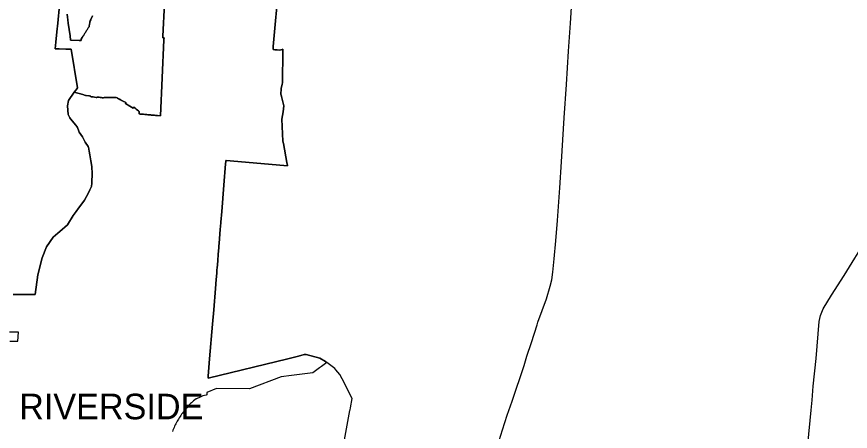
# Model space of a CAD drawing. Extents: x 0 to 34, y 0 to 22.
# Drawn here: x 5.3732 to 5.6354, y 15.5639 to 15.6943 of the extents above; entities that cross this region are included whole.
import ezdxf

# ---------------------------------------------------------------- set-up
doc = ezdxf.new("R2010")
doc.units = 0
for name, color, linetype in [('GM_X_Corporation', 7, 'Continuous'), ('GM_X_Corporation_Text', 7, 'Continuous'), ('GM_X_State_Route', 7, 'Continuous')]:
    doc.layers.add(name, color=color, linetype=linetype)

msp = doc.modelspace()

# ---------------------------------------------------------------- linework, layer by layer
at = {"layer": 'GM_X_Corporation'}
for points in [[(5.45565, 15.70458), (5.45394, 15.68495), (5.4539, 15.68447), (5.45386, 15.68399), (5.45443, 15.68394), (5.45515, 15.68387), (5.45602, 15.68379), (5.45634, 15.6839), (5.45641, 15.68392), (5.45695, 15.6841), (5.45695, 15.68396), (5.45695, 15.68351), (5.45688, 15.67362), (5.45688, 15.67347), (5.45677, 15.6731), (5.45639, 15.67177), (5.45634, 15.66989), (5.45638, 15.66974), (5.45652, 15.66919), (5.45729, 15.66627), (5.45701, 15.66442), (5.45665, 15.6621), (5.45698, 15.65516), (5.45712, 15.65441), (5.45825, 15.64847), (5.45836, 15.64789), (5.45841, 15.64761), (5.45844, 15.64743), (5.4573, 15.64753), (5.43915, 15.64911), (5.43903, 15.64912), (5.43899, 15.64863), (5.43895, 15.64815), (5.43895, 15.64807), (5.4384, 15.64136), (5.43772, 15.63301), (5.43745, 15.62972), (5.43743, 15.62943), (5.43726, 15.62736), (5.43691, 15.62308), (5.43689, 15.6229), (5.43685, 15.62235), (5.43679, 15.62162), (5.43662, 15.6196), (5.43646, 15.61754), (5.43627, 15.61522), (5.43623, 15.61475), (5.43621, 15.61449), (5.4362, 15.61442), (5.43616, 15.61396), (5.43614, 15.61362), (5.43598, 15.61164), (5.43575, 15.60878), (5.43526, 15.60216), (5.43525, 15.60208), (5.43481, 15.59761), (5.43393, 15.58667), (5.43349, 15.58122), (5.43344, 15.58058), (5.45847, 15.58674), (5.46192, 15.58759), (5.46369, 15.58803), (5.46388, 15.58808), (5.46428, 15.58803), (5.46854, 15.5869), (5.47038, 15.58585), (5.47043, 15.5858), (5.47076, 15.5855), (5.47037, 15.58523), (5.46908, 15.58432), (5.46848, 15.58389), (5.46641, 15.58228), (5.4597, 15.58146), (5.45643, 15.58102), (5.44643, 15.57724), (5.43612, 15.57736), (5.43307, 15.57609), (5.43301, 15.57535), (5.43285, 15.57531), (5.4318, 15.57508), (5.43091, 15.57466), (5.42976, 15.57412), (5.42972, 15.5741), (5.42882, 15.57347), (5.42854, 15.57321), (5.42853, 15.57321), (5.42822, 15.57291), (5.4279, 15.5726), (5.4276, 15.57229), (5.4273, 15.57198), (5.427, 15.57165), (5.42671, 15.57133), (5.42643, 15.571), (5.42615, 15.57066), (5.42588, 15.57032), (5.42561, 15.56997), (5.42536, 15.56962), (5.4251, 15.56927), (5.42485, 15.56891), (5.42461, 15.56854), (5.42438, 15.56818), (5.42413, 15.56777), (5.42393, 15.56743), (5.42371, 15.56705), (5.42351, 15.56666), (5.4233, 15.56628), (5.42311, 15.56589), (5.42292, 15.56549), (5.42274, 15.5651), (5.42257, 15.5647), (5.4224, 15.56429), (5.42224, 15.56389)], [(5.4763, 15.56125), (5.47806, 15.57044), (5.4781, 15.57063), (5.47823, 15.57133), (5.47878, 15.5742), (5.4756, 15.58039), (5.47483, 15.58178), (5.47364, 15.5832), (5.4733, 15.58361), (5.47076, 15.5855), (5.47043, 15.5858), (5.47038, 15.58585), (5.46854, 15.5869), (5.46428, 15.58803), (5.46388, 15.58808), (5.46369, 15.58803), (5.46192, 15.58759), (5.45847, 15.58674), (5.43344, 15.58058), (5.43349, 15.58122), (5.43393, 15.58667), (5.43481, 15.59761), (5.43525, 15.60208), (5.43526, 15.60216), (5.43575, 15.60878), (5.43598, 15.61164), (5.43614, 15.61362), (5.43616, 15.61396), (5.43621, 15.61449), (5.43623, 15.61475), (5.43627, 15.61522), (5.43646, 15.61754), (5.43662, 15.6196), (5.43679, 15.62162), (5.43685, 15.62235), (5.43689, 15.6229), (5.43691, 15.62308), (5.43726, 15.62736), (5.43743, 15.62943), (5.43745, 15.62972), (5.43772, 15.63301), (5.4384, 15.64136), (5.43895, 15.64807), (5.43895, 15.64815), (5.43899, 15.64863), (5.43903, 15.64912), (5.43915, 15.64911), (5.4573, 15.64753), (5.45844, 15.64743), (5.45841, 15.64761), (5.45836, 15.64789), (5.45825, 15.64847), (5.45712, 15.65441), (5.45698, 15.65516), (5.45665, 15.6621), (5.45701, 15.66442), (5.45729, 15.66627), (5.45652, 15.66919), (5.45638, 15.66974), (5.45634, 15.66989), (5.45639, 15.67177), (5.45677, 15.6731), (5.45688, 15.67347), (5.45688, 15.67362), (5.45695, 15.68351), (5.45695, 15.68396), (5.45695, 15.6841), (5.45641, 15.68392), (5.45634, 15.6839), (5.45602, 15.68379), (5.45515, 15.68387), (5.45443, 15.68394), (5.45386, 15.68399), (5.45394, 15.68495), (5.45565, 15.70458)], [(5.37215, 15.60695), (5.37461, 15.60695), (5.37468, 15.60695), (5.37697, 15.60695), (5.37715, 15.60694), (5.37758, 15.60694), (5.37797, 15.60694), (5.37819, 15.60694), (5.37908, 15.60694), (5.37994, 15.61307), (5.38121, 15.61847), (5.38261, 15.62195), (5.38467, 15.62497), (5.38618, 15.62627), (5.38678, 15.62679), (5.38917, 15.62886), (5.39099, 15.63177), (5.3919, 15.633), (5.39273, 15.63414), (5.39305, 15.63457), (5.39457, 15.63664), (5.39521, 15.63774), (5.39528, 15.63785), (5.39624, 15.63982), (5.39675, 15.64086), (5.39682, 15.64195), (5.39684, 15.64223), (5.39699, 15.64486), (5.39687, 15.64725), (5.3966, 15.64894), (5.39623, 15.65087), (5.39602, 15.65198), (5.39578, 15.65324), (5.39572, 15.65354), (5.3948, 15.65487), (5.39389, 15.65652), (5.39292, 15.65801), (5.39281, 15.65818), (5.39277, 15.65832), (5.3924, 15.65943), (5.39215, 15.65979), (5.39185, 15.66023), (5.39011, 15.66222), (5.38997, 15.6625), (5.38944, 15.66353), (5.38918, 15.66628), (5.38951, 15.66794), (5.39136, 15.67053), (5.39407, 15.6698), (5.3949, 15.66957), (5.39506, 15.66953), (5.39588, 15.66941), (5.39607, 15.66939), (5.39612, 15.66938), (5.39631, 15.66936), (5.39643, 15.66934), (5.3966, 15.66932), (5.39658, 15.66916), (5.39665, 15.66915), (5.39678, 15.66913), (5.39725, 15.66906), (5.39773, 15.669), (5.39821, 15.66893), (5.39849, 15.6689), (5.39851, 15.66905), (5.3987, 15.66903), (5.39899, 15.66899), (5.39918, 15.66896), (5.39947, 15.66892), (5.39966, 15.6689), (5.39994, 15.66886), (5.40013, 15.66883), (5.40055, 15.66884), (5.40074, 15.66885), (5.40103, 15.66885), (5.40122, 15.66886), (5.40152, 15.66886), (5.4017, 15.66887), (5.402, 15.66887), (5.40219, 15.66888), (5.40248, 15.66888), (5.40267, 15.66889), (5.40296, 15.66889), (5.40315, 15.6689), (5.40344, 15.6689), (5.40363, 15.66891), (5.40393, 15.66891), (5.40411, 15.66892), (5.40438, 15.66892), (5.40446, 15.66892), (5.40456, 15.66887), (5.40479, 15.66875), (5.40494, 15.66867), (5.40522, 15.66853), (5.40537, 15.66845), (5.40564, 15.66831), (5.4058, 15.66823), (5.40607, 15.66809), (5.40622, 15.66801), (5.4065, 15.66787), (5.40665, 15.66779), (5.40672, 15.66776), (5.40687, 15.66768), (5.40714, 15.66754), (5.40734, 15.66744), (5.40757, 15.66731), (5.40742, 15.66703), (5.40878, 15.6662), (5.40982, 15.66556), (5.41007, 15.66587), (5.4101, 15.66585), (5.41045, 15.66557), (5.41048, 15.66555), (5.41083, 15.66528), (5.41086, 15.66525), (5.41124, 15.66495), (5.41154, 15.66472), (5.41176, 15.66455), (5.41176, 15.66452), (5.41172, 15.66374), (5.4121, 15.66371), (5.4122, 15.6637), (5.41258, 15.66366), (5.41268, 15.66365), (5.41306, 15.66362), (5.41316, 15.66361), (5.41354, 15.66358), (5.41364, 15.66357), (5.41402, 15.66353), (5.41412, 15.66352), (5.4145, 15.66349), (5.4146, 15.66348), (5.41498, 15.66344), (5.41508, 15.66343), (5.41546, 15.6634), (5.41556, 15.66339), (5.41594, 15.66336), (5.41605, 15.66335), (5.41642, 15.66331), (5.41653, 15.6633), (5.4169, 15.66327), (5.41701, 15.66326), (5.41746, 15.66322), (5.41749, 15.66321), (5.41842, 15.66313), (5.41955, 15.68699), (5.41956, 15.68706), (5.41956, 15.68715), (5.41958, 15.68763), (5.41917, 15.68767), (5.41917, 15.68767), (5.4192, 15.68816), (5.4197, 15.69842)], [(5.4197, 15.69842), (5.4192, 15.68816), (5.41917, 15.68767), (5.41917, 15.68767), (5.41958, 15.68763), (5.41956, 15.68715), (5.41956, 15.68706), (5.41955, 15.68699), (5.41842, 15.66313), (5.41749, 15.66321), (5.41746, 15.66322), (5.41701, 15.66326), (5.4169, 15.66327), (5.41653, 15.6633), (5.41642, 15.66331), (5.41605, 15.66335), (5.41594, 15.66336), (5.41556, 15.66339), (5.41546, 15.6634), (5.41508, 15.66343), (5.41498, 15.66344), (5.4146, 15.66348), (5.4145, 15.66349), (5.41412, 15.66352), (5.41402, 15.66353), (5.41364, 15.66357), (5.41354, 15.66358), (5.41316, 15.66361), (5.41306, 15.66362), (5.41268, 15.66365), (5.41258, 15.66366), (5.4122, 15.6637), (5.4121, 15.66371), (5.41172, 15.66374), (5.41176, 15.66452), (5.41176, 15.66455), (5.41154, 15.66472), (5.41124, 15.66495), (5.41086, 15.66525), (5.41083, 15.66528), (5.41048, 15.66555), (5.41045, 15.66557), (5.4101, 15.66585), (5.41007, 15.66587), (5.40982, 15.66556), (5.40878, 15.6662), (5.40742, 15.66703), (5.40757, 15.66731), (5.40734, 15.66744), (5.40714, 15.66754), (5.40687, 15.66768), (5.40672, 15.66776), (5.40665, 15.66779), (5.4065, 15.66787), (5.40622, 15.66801), (5.40607, 15.66809), (5.4058, 15.66823), (5.40564, 15.66831), (5.40537, 15.66845), (5.40522, 15.66853), (5.40494, 15.66867), (5.40479, 15.66875), (5.40456, 15.66887), (5.40446, 15.66892), (5.40438, 15.66892), (5.40411, 15.66892), (5.40393, 15.66891), (5.40363, 15.66891), (5.40344, 15.6689), (5.40315, 15.6689), (5.40296, 15.66889), (5.40267, 15.66889), (5.40248, 15.66888), (5.40219, 15.66888), (5.402, 15.66887), (5.4017, 15.66887), (5.40152, 15.66886), (5.40122, 15.66886), (5.40103, 15.66885), (5.40074, 15.66885), (5.40055, 15.66884), (5.40013, 15.66883), (5.39994, 15.66886), (5.39966, 15.6689), (5.39947, 15.66892), (5.39918, 15.66896), (5.39899, 15.66899), (5.3987, 15.66903), (5.39851, 15.66905), (5.39849, 15.6689), (5.39821, 15.66893), (5.39773, 15.669), (5.39725, 15.66906), (5.39678, 15.66913), (5.39665, 15.66915), (5.39658, 15.66916), (5.3966, 15.66932), (5.39643, 15.66934), (5.39631, 15.66936), (5.39612, 15.66938), (5.39607, 15.66939), (5.39588, 15.66941), (5.39506, 15.66953), (5.3949, 15.66957), (5.39407, 15.6698), (5.39136, 15.67053), (5.39196, 15.67136), (5.3924, 15.67197), (5.39032, 15.68413), (5.38967, 15.68413), (5.38872, 15.68415), (5.38662, 15.68417), (5.38658, 15.68417), (5.38531, 15.68419), (5.38552, 15.68626), (5.38584, 15.68951), (5.38613, 15.69231), (5.38669, 15.69795)], [(5.38669, 15.69795), (5.38613, 15.69231), (5.38584, 15.68951), (5.38552, 15.68626), (5.38531, 15.68419), (5.38658, 15.68417), (5.38662, 15.68417), (5.38872, 15.68415), (5.38967, 15.68413), (5.39032, 15.68413), (5.3924, 15.67197), (5.39196, 15.67136), (5.39136, 15.67053), (5.38951, 15.66794), (5.38918, 15.66628), (5.38944, 15.66353), (5.38997, 15.6625), (5.39011, 15.66222), (5.39185, 15.66023), (5.39215, 15.65979), (5.3924, 15.65943), (5.39277, 15.65832), (5.39281, 15.65818), (5.39292, 15.65801), (5.39389, 15.65652), (5.3948, 15.65487), (5.39572, 15.65354), (5.39578, 15.65324), (5.39602, 15.65198), (5.39623, 15.65087), (5.3966, 15.64894), (5.39687, 15.64725), (5.39699, 15.64486), (5.39684, 15.64223), (5.39682, 15.64195), (5.39675, 15.64086), (5.39624, 15.63982), (5.39528, 15.63785), (5.39521, 15.63774), (5.39457, 15.63664), (5.39305, 15.63457), (5.39273, 15.63414), (5.3919, 15.633), (5.39099, 15.63177), (5.38917, 15.62886), (5.38678, 15.62679), (5.38618, 15.62627), (5.38467, 15.62497), (5.38261, 15.62195), (5.38121, 15.61847), (5.37994, 15.61307), (5.37908, 15.60694), (5.37819, 15.60694), (5.37797, 15.60694), (5.37758, 15.60694), (5.37715, 15.60694), (5.37697, 15.60695), (5.37468, 15.60695), (5.37461, 15.60695), (5.3742, 15.60695), (5.37215, 15.60695)], [(5.38907, 15.69508), (5.38944, 15.69233), (5.39008, 15.68827), (5.39015, 15.68692), (5.39287, 15.68681), (5.3932, 15.68679), (5.39325, 15.68679), (5.39342, 15.68679), (5.39355, 15.68678), (5.39353, 15.68703), (5.39352, 15.68716), (5.39351, 15.68724), (5.39383, 15.68774), (5.3939, 15.68785), (5.39395, 15.68792), (5.39409, 15.68815), (5.3942, 15.68833), (5.39435, 15.68856), (5.39446, 15.68873), (5.39461, 15.68897), (5.39472, 15.68914), (5.39487, 15.68937), (5.39498, 15.68955), (5.39513, 15.68978), (5.39524, 15.68996), (5.39539, 15.69019), (5.3955, 15.69037), (5.39564, 15.69059), (5.39576, 15.69078), (5.3959, 15.691), (5.396, 15.69115), (5.396, 15.69118), (5.39607, 15.69155), (5.39611, 15.6918), (5.39615, 15.69205), (5.3962, 15.69233), (5.39623, 15.69254), (5.39628, 15.69281), (5.3963, 15.69285), (5.39637, 15.69301), (5.39651, 15.6933), (5.39658, 15.69345), (5.39671, 15.69373), (5.39678, 15.69388), (5.39692, 15.69417), (5.39699, 15.69432), (5.39712, 15.69461)], [(5.39712, 15.69461), (5.39699, 15.69432), (5.39692, 15.69417), (5.39678, 15.69388), (5.39671, 15.69373), (5.39658, 15.69345), (5.39651, 15.6933), (5.39637, 15.69301), (5.3963, 15.69285), (5.39628, 15.69281), (5.39623, 15.69254), (5.3962, 15.69233), (5.39615, 15.69205), (5.39611, 15.6918), (5.39607, 15.69155), (5.396, 15.69118), (5.396, 15.69115), (5.3959, 15.691), (5.39576, 15.69078), (5.39564, 15.69059), (5.3955, 15.69037), (5.39539, 15.69019), (5.39524, 15.68996), (5.39513, 15.68978), (5.39498, 15.68955), (5.39487, 15.68937), (5.39472, 15.68914), (5.39461, 15.68897), (5.39446, 15.68873), (5.39435, 15.68856), (5.3942, 15.68833), (5.39409, 15.68815), (5.39395, 15.68792), (5.3939, 15.68785), (5.39383, 15.68774), (5.39351, 15.68724), (5.39352, 15.68716), (5.39353, 15.68703), (5.39355, 15.68678), (5.39342, 15.68679), (5.39325, 15.68679), (5.3932, 15.68679), (5.39287, 15.68681), (5.39015, 15.68692), (5.39008, 15.68827), (5.38944, 15.69233), (5.38944, 15.69235), (5.38907, 15.69508)], [(5.37103, 15.59224), (5.3736, 15.59223), (5.37382, 15.59506), (5.37357, 15.59506), (5.37095, 15.59505)]]:
    msp.add_lwpolyline(points, dxfattribs=at)
at = {"layer": 'GM_X_State_Route'}
for points in [[(5.53692, 15.59741), (5.53717, 15.59821), (5.53983, 15.60554), (5.54105, 15.60953), (5.54157, 15.61158), (5.54191, 15.614), (5.54232, 15.61817), (5.54277, 15.62385), (5.54335, 15.63026), (5.54405, 15.64045), (5.5446, 15.64867), (5.54548, 15.6625), (5.54615, 15.67294), (5.54682, 15.68345), (5.54745, 15.69224), (5.54784, 15.69885)], [(5.62097, 15.54895), (5.62309, 15.57055), (5.6234, 15.57374), (5.62378, 15.57814), (5.6247, 15.58677), (5.62565, 15.59848), (5.62609, 15.60031), (5.62643, 15.60135), (5.62694, 15.60247), (5.62955, 15.60668), (5.63349, 15.61287), (5.63687, 15.61836), (5.63897, 15.62168), (5.63966, 15.62289), (5.64344, 15.63235), (5.64829, 15.64395), (5.65026, 15.64896), (5.65278, 15.65527), (5.65574, 15.66279), (5.65676, 15.66542), (5.65708, 15.66628), (5.6583, 15.66849), (5.65858, 15.66902)], [(5.52348, 15.55637), (5.52379, 15.55746), (5.525, 15.561), (5.52602, 15.56436), (5.5275, 15.56897), (5.52911, 15.5734), (5.53285, 15.5846), (5.53374, 15.58749), (5.53518, 15.59183), (5.53692, 15.59741)]]:
    msp.add_lwpolyline(points, dxfattribs=at)

# ---------------------------------------------------------------- texts
at = {"layer": 'GM_X_Corporation_Text'}
msp.add_text('RIVERSIDE', height=0.008037, rotation=0, dxfattribs=at).set_placement((5.37402, 15.56769))

doc.saveas('drawing.dxf')
